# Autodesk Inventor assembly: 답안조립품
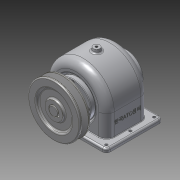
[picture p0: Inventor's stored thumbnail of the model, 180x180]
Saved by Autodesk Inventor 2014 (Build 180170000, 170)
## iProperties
Created: 2015-09
Part Number: 답안조립품
Document SubType Name: Assembly
Designer: basic
Author: basic
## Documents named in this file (14)
- C:\Users\basic\Desktop\450907V1030\답안조립품.iam
- C:\Users\basic\Desktop\450907V1030\답안본체.ipt
- C:\Users\basic\Desktop\450907V1030\V-벨트풀리.ipt
- C:\Users\basic\Desktop\450907V1030\뒤커버.ipt
- C:\Users\basic\Desktop\450907V1030\멈춤나사 - M4x10.ipt
- C:\Users\basic\Desktop\450907V1030\베어링 6203.ipt
- C:\Users\basic\Desktop\450907V1030\볼트 M3 x 8.ipt
- C:\Users\basic\Desktop\450907V1030\볼트 M3 x 10.ipt
- C:\Users\basic\Desktop\450907V1030\스퍼기어.ipt
- C:\Users\basic\Desktop\450907V1030\앞커버.ipt
- C:\Users\basic\Desktop\450907V1030\오일 실 17 32 8.ipt
- C:\Users\basic\Desktop\450907V1030\축.ipt
- C:\Users\basic\Desktop\450907V1030\키 - 5 x 5 x 18.ipt
- C:\Users\basic\Desktop\450907V1030\키 - 6 x 6 x 22.ipt
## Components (9 placed, 3 different names)
1. V-벨트풀리:1
2. ISO 4762 M3 x 8:1
3. ISO 4762 M3 x 8:2
4. ISO 4762 M3 x 8:3
5. ISO 4762 M3 x 8:4
6. ISO 4762 M3 x 10:1
7. ISO 4762 M3 x 10:2
8. ISO 4762 M3 x 10:3
9. ISO 4762 M3 x 10:4
